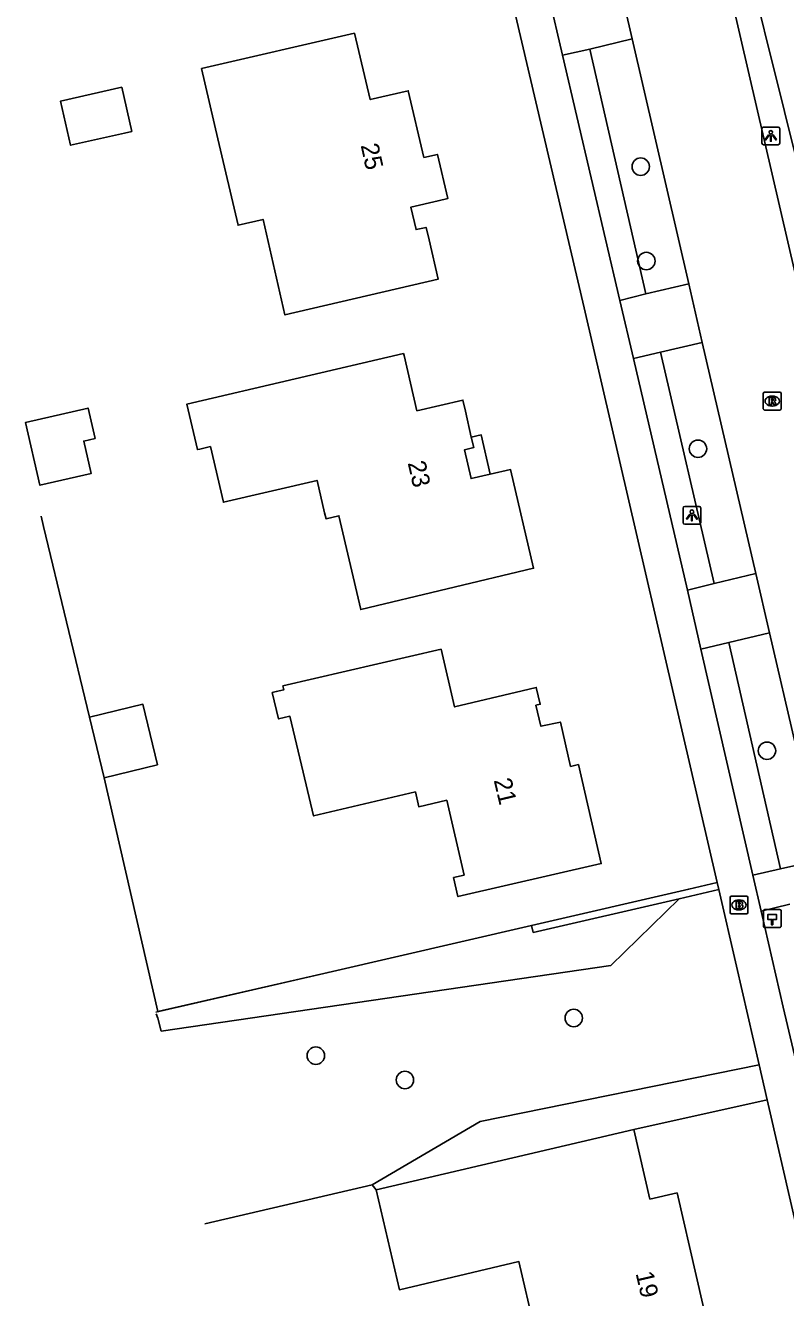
# Model space of a CAD drawing. Extents: x 156414 to 157775, y 382335 to 383765.
# Drawn here: x 156686.2 to 156728.9, y 382611 to 382682.4 of the extents above; entities that cross this region are included whole.
import ezdxf

# ---------------------------------------------------------------- set-up
doc = ezdxf.new("R2010")
doc.units = 0
for name, color, linetype in [('IMGEO_Boom', 7, 'Continuous'), ('IMGEO_Brandkraan', 7, 'Continuous'), ('IMGEO_Greppel_droge_sloot', 7, 'Continuous'), ('IMGEO_Groenvoorziening', 7, 'Continuous'), ('IMGEO_Haag', 7, 'Continuous'), ('IMGEO_Hectometerpaal', 7, 'Continuous'), ('IMGEO_Hek', 7, 'Continuous'), ('IMGEO_Lichtpunt', 7, 'Continuous'), ('IMGEO_Pand', 7, 'Continuous'), ('IMGEO_Pand_nummerreeks', 7, 'Continuous'), ('IMGEO_Pand_overbouw', 7, 'Continuous'), ('IMGEO_Parkeervlak_halfverhard', 7, 'Continuous'), ('IMGEO_Rijbaan_lokaal_gesloten', 7, 'Continuous'), ('IMGEO_Rijbaan_lokaal_open', 7, 'Continuous'), ('IMGEO_Rioolput', 7, 'Continuous'), ('IMGEO_Voetpad_open', 7, 'Continuous')]:
    doc.layers.add(name, color=color, linetype=linetype)

msp = doc.modelspace()

# ---------------------------------------------------------------- linework, layer by layer
at = {"layer": 'IMGEO_Boom'}
for centre in [(156720.732, 382674.429), (156721.049, 382669.132), (156723.946, 382658.599), (156727.819, 382641.649), (156716.972, 382626.649), (156702.493, 382624.535), (156707.495, 382623.172)]:
    msp.add_circle(centre, 0.489, dxfattribs=at)
at = {"layer": 'IMGEO_Brandkraan'}
for p, q in [((156725.749, 382632.57), (156725.749, 382633.422)), ((156725.824, 382633.496), (156726.676, 382633.496)), ((156726.237, 382633.276), (156726.262, 382633.276)), ((156726.75, 382633.422), (156726.75, 382632.57)), ((156726.676, 382632.496), (156725.824, 382632.496)), ((156726.26, 382632.716), (156726.235, 382632.716))]:
    msp.add_line(p, q, dxfattribs=at)
for points in [[(156725.749, 382632.57), (156725.749, 382633.422)], [(156725.824, 382633.496), (156726.676, 382633.496)], [(156726.097, 382633.196), (156726.097, 382632.796), (156726.31, 382632.796)], [(156726.328, 382633.196), (156726.097, 382633.196)], [(156726.276, 382633.115), (156726.222, 382633.115), (156726.222, 382633.039)], [(156726.222, 382633.039), (156726.275, 382633.039)], [(156726.75, 382633.422), (156726.75, 382632.57)], [(156726.676, 382632.496), (156725.824, 382632.496)], [(156726.284, 382632.963), (156726.222, 382632.963), (156726.222, 382632.882)], [(156726.222, 382632.882), (156726.284, 382632.882)]]:
    msp.add_lwpolyline(points, dxfattribs=at)
for centre, radius, start, end in [((156725.826, 382633.42), 0.0765, 91.55205, 178.44795), ((156725.826, 382633.42), 0.0765, 91.55205, 178.44795), ((156726.277, 382633.077), 0.0379, 267.82845, 90.93552), ((156726.332, 382633.051), 0.145, 59.4692, 91.53667), ((156726.357, 382633.098), 0.0922, 285.51372, 58.15012), ((156726.362, 382632.906), 0.105, 301.31148, 78.98903), ((156726.674, 382633.42), 0.0765, 1.55205, 88.44795), ((156726.674, 382633.42), 0.0765, 1.55205, 88.44795), ((156725.826, 382632.572), 0.0765, 181.55205, 268.44795), ((156725.826, 382632.572), 0.0765, 181.55205, 268.44795), ((156726.285, 382632.922), 0.0404, 269.87594, 90.50774), ((156726.316, 382633.047), 0.251, 268.66757, 293.53466), ((156726.674, 382632.572), 0.0765, 271.55205, 358.44795), ((156726.674, 382632.572), 0.0765, 271.55205, 358.44795)]:
    msp.add_arc(centre, radius, start, end, dxfattribs=at)
for centre, major_axis, ratio, start_param, end_param in [((156726.236, 382632.996), (-0.387, 0.002), 0.722429, 4.712389, 7.853982), ((156726.261, 382632.996), (-0.39, 0.002), 0.717154, 1.570796, 4.712389)]:
    msp.add_ellipse(centre, major_axis=major_axis, ratio=ratio, start_param=start_param, end_param=end_param, dxfattribs=at)
at = {"layer": 'IMGEO_Greppel_droge_sloot'}
msp.add_lwpolyline([(156737.852, 382641.163), (156726.53, 382686.636)], dxfattribs=at)
at = {"layer": 'IMGEO_Groenvoorziening'}
for points in [[(156693.53, 382626.892), (156693.617, 382626.638), (156693.819, 382625.918), (156719.051, 382629.606), (156722.881, 382633.345)], [(156693.51, 382626.977), (156703.184, 382629.211), (156714.604, 382631.846)], [(156705.651, 382617.283), (156711.711, 382620.85), (156727.385, 382624.03)], [(156727.839, 382622.057), (156720.348, 382620.401)], [(156705.651, 382617.283), (156696.258, 382615.091)], [(156705.872, 382617.015), (156705.651, 382617.283)]]:
    msp.add_lwpolyline(points, dxfattribs=at)
at = {"layer": 'IMGEO_Haag'}
for points in [[(156714.604, 382631.846), (156723.432, 382633.883), (156725.025, 382634.25)], [(156725.115, 382633.86), (156722.881, 382633.345)], [(156722.881, 382633.345), (156714.694, 382631.456), (156714.604, 382631.846)]]:
    msp.add_lwpolyline(points, dxfattribs=at)
at = {"layer": 'IMGEO_Hectometerpaal'}
for p, q in [((156727.617, 382632.648), (156727.617, 382631.807)), ((156727.617, 382632.648), (156727.617, 382631.807)), ((156728.533, 382632.732), (156727.692, 382632.732)), ((156728.533, 382632.732), (156727.692, 382632.732)), ((156728.617, 382631.816), (156728.617, 382632.657)), ((156728.617, 382631.816), (156728.617, 382632.657)), ((156727.701, 382631.732), (156728.542, 382631.732)), ((156727.701, 382631.732), (156728.542, 382631.732))]:
    msp.add_line(p, q, dxfattribs=at)
msp.add_lwpolyline([(156728.142, 382631.876), (156728.082, 382631.876), (156728.082, 382632.181), (156727.862, 382632.181), (156727.862, 382632.45), (156728.362, 382632.45), (156728.362, 382632.181), (156728.142, 382632.181), (156728.142, 382631.876)], dxfattribs=at)
for centre, start, end in [((156727.695, 382632.654), 92.4484, 184.28452), ((156727.695, 382632.654), 92.4484, 184.28452), ((156728.539, 382632.654), 2.4484, 94.28452), ((156728.539, 382632.654), 2.4484, 94.28452), ((156727.695, 382631.81), 182.4484, 274.28452), ((156727.695, 382631.81), 182.4484, 274.28452), ((156728.539, 382631.81), 272.4484, 4.28452), ((156728.539, 382631.81), 272.4484, 4.28452)]:
    msp.add_arc(centre, 0.0779, start, end, dxfattribs=at)
at = {"layer": 'IMGEO_Hek'}
for points in [[(156687.072, 382654.823), (156687.21, 382654.227)], [(156687.21, 382654.227), (156689.788, 382643.539)], [(156693.632, 382627.007), (156690.609, 382640.137)], [(156703.184, 382629.211), (156714.604, 382631.846)], [(156693.632, 382627.007), (156703.184, 382629.211)]]:
    msp.add_lwpolyline(points, dxfattribs=at)
at = {"layer": 'IMGEO_Lichtpunt'}
for p, q in [((156727.537, 382676.558), (156727.537, 382675.751)), ((156727.537, 382676.558), (156727.537, 382675.751)), ((156728.439, 382676.653), (156727.631, 382676.653)), ((156728.439, 382676.653), (156727.631, 382676.653)), ((156728.533, 382675.751), (156728.533, 382676.558)), ((156728.533, 382675.751), (156728.533, 382676.558)), ((156727.631, 382675.657), (156728.439, 382675.657)), ((156727.631, 382675.657), (156728.439, 382675.657)), ((156723.106, 382655.264), (156723.106, 382654.457)), ((156723.106, 382655.264), (156723.106, 382654.457)), ((156724.008, 382655.359), (156723.2, 382655.359)), ((156724.008, 382655.359), (156723.2, 382655.359)), ((156724.102, 382654.457), (156724.102, 382655.264)), ((156724.102, 382654.457), (156724.102, 382655.264)), ((156723.2, 382654.363), (156724.008, 382654.363)), ((156723.2, 382654.363), (156724.008, 382654.363))]:
    msp.add_line(p, q, dxfattribs=at)
for points in [[(156727.911, 382676.222), (156727.95, 382676.194), (156727.762, 382675.932), (156727.724, 382675.959), (156727.911, 382676.222)], [(156728.013, 382676.174), (156728.06, 382676.174), (156728.06, 382675.852), (156728.013, 382675.852), (156728.013, 382676.174)], [(156728.123, 382676.194), (156728.161, 382676.221), (156728.348, 382675.959), (156728.309, 382675.931), (156728.123, 382676.194)], [(156723.48, 382654.928), (156723.519, 382654.9), (156723.331, 382654.638), (156723.293, 382654.665), (156723.48, 382654.928)], [(156723.582, 382654.88), (156723.629, 382654.88), (156723.629, 382654.558), (156723.582, 382654.558), (156723.582, 382654.88)], [(156723.692, 382654.9), (156723.73, 382654.927), (156723.917, 382654.665), (156723.878, 382654.637), (156723.692, 382654.9)]]:
    msp.add_lwpolyline(points, dxfattribs=at)
for centre in [(156728.036, 382676.356), (156723.605, 382655.062)]:
    msp.add_circle(centre, 0.0994, dxfattribs=at)
for centre, start, end in [((156727.631, 382676.558), 90, 180), ((156727.631, 382676.558), 90, 180), ((156728.439, 382676.558), 0, 90), ((156728.439, 382676.558), 0, 90), ((156727.631, 382675.751), 180, 270), ((156727.631, 382675.751), 180, 270), ((156728.439, 382675.751), 270, 0), ((156728.439, 382675.751), 270, 360), ((156723.2, 382655.264), 90, 180), ((156723.2, 382655.264), 90, 180), ((156724.008, 382655.264), 0, 90), ((156724.008, 382655.264), 0, 90), ((156723.2, 382654.457), 180, 270), ((156723.2, 382654.457), 180, 270), ((156724.008, 382654.457), 270, 0), ((156724.008, 382654.457), 270, 360)]:
    msp.add_arc(centre, 0.0946, start, end, dxfattribs=at)
at = {"layer": 'IMGEO_Pand'}
for points in [[(156704.657, 382681.914), (156705.551, 382678.197), (156707.683, 382678.692), (156708.562, 382674.946), (156709.317, 382675.112), (156709.897, 382672.638), (156709.358, 382672.512), (156707.825, 382672.152), (156708.119, 382670.899), (156708.682, 382671.021), (156708.846, 382670.326), (156709.367, 382668.117), (156700.76, 382666.11), (156699.534, 382671.469), (156698.128, 382671.144), (156696.997, 382675.993), (156696.078, 382679.932), (156704.657, 382681.914)], [(156691.594, 382678.892), (156692.159, 382676.409), (156691.748, 382676.315), (156688.723, 382675.628), (156688.16, 382678.114), (156691.594, 382678.892)], [(156707.418, 382663.946), (156707.443, 382663.84), (156708.171, 382660.726), (156710.749, 382661.332), (156710.889, 382660.713), (156711.222, 382659.249), (156711.355, 382658.664), (156710.839, 382658.546), (156711.211, 382656.927), (156712.281, 382657.173), (156713.429, 382657.43), (156714.719, 382651.887), (156705.019, 382649.572), (156703.787, 382654.84), (156703.066, 382654.671), (156702.987, 382655.01), (156702.563, 382656.823), (156697.305, 382655.593), (156696.574, 382658.719), (156695.981, 382658.58), (156695.843, 382658.548), (156695.247, 382661.099), (156707.418, 382663.946)], [(156690.102, 382659.172), (156689.468, 382659.026), (156689.887, 382657.213), (156687.003, 382656.547), (156686.19, 382660.065), (156689.708, 382660.877), (156690.102, 382659.172)], [(156708.083, 382639.34), (156702.365, 382637.988), (156701.782, 382640.455), (156701.041, 382643.589), (156700.398, 382643.437), (156700.048, 382644.916), (156700.269, 382644.968), (156700.697, 382645.069), (156700.647, 382645.283), (156709.527, 382647.347), (156710.278, 382644.11), (156714.07, 382645.013), (156714.87, 382645.204), (156715.091, 382644.257), (156714.848, 382644.201), (156715.127, 382643.024), (156716.228, 382643.258), (156716.796, 382640.77), (156717.234, 382640.87), (156718.513, 382635.315), (156710.474, 382633.463), (156710.227, 382634.535), (156710.812, 382634.67), (156709.844, 382638.87), (156708.275, 382638.508), (156708.083, 382639.34)], [(156693.61, 382640.861), (156690.609, 382640.137), (156689.788, 382643.539), (156692.789, 382644.263), (156693.61, 382640.861)], [(156720.348, 382620.401), (156721.249, 382616.488), (156722.772, 382616.838), (156724.915, 382607.561), (156715.64, 382605.418), (156713.892, 382612.982), (156707.186, 382611.397), (156705.872, 382617.015)], [(156705.872, 382617.015), (156720.348, 382620.401)]]:
    msp.add_lwpolyline(points, dxfattribs=at)
at = {"layer": 'IMGEO_Pand_overbouw'}
msp.add_lwpolyline([(156712.281, 382657.173), (156711.779, 382659.373), (156711.222, 382659.249), (156711.355, 382658.664), (156710.839, 382658.546), (156711.211, 382656.927)], close=True, dxfattribs=at)
at = {"layer": 'IMGEO_Parkeervlak_halfverhard'}
for points in [[(156717.872, 382681.03), (156721.027, 382667.291)], [(156721.845, 382664.018), (156724.862, 382651.027)], [(156725.682, 382647.725), (156728.587, 382635.019)]]:
    msp.add_lwpolyline(points, dxfattribs=at)
at = {"layer": 'IMGEO_Rijbaan_lokaal_gesloten'}
for points in [[(156736.553, 382637.563), (156725.004, 382687.432)], [(156720.255, 382681.599), (156719.479, 382684.929)], [(156723.431, 382667.857), (156720.255, 382681.599)], [(156724.186, 382664.553), (156723.431, 382667.857)], [(156727.193, 382651.603), (156724.186, 382664.553)], [(156727.963, 382648.268), (156727.193, 382651.603)], [(156730.916, 382635.549), (156727.963, 382648.268)]]:
    msp.add_lwpolyline(points, dxfattribs=at)
at = {"layer": 'IMGEO_Rijbaan_lokaal_open'}
for points in [[(156715.565, 382684.002), (156716.343, 382680.694)], [(156720.255, 382681.599), (156717.872, 382681.03)], [(156716.343, 382680.694), (156717.872, 382681.03)], [(156721.027, 382667.291), (156719.564, 382666.914)], [(156721.027, 382667.291), (156723.431, 382667.857)], [(156719.564, 382666.914), (156720.326, 382663.671)], [(156724.186, 382664.553), (156721.845, 382664.018)], [(156720.326, 382663.671), (156721.845, 382664.018)], [(156724.862, 382651.027), (156727.193, 382651.603)], [(156724.862, 382651.027), (156723.353, 382650.655)], [(156723.353, 382650.655), (156724.101, 382647.349)], [(156727.963, 382648.268), (156725.682, 382647.725)], [(156724.101, 382647.349), (156725.682, 382647.725)]]:
    msp.add_lwpolyline(points, dxfattribs=at)
at = {"layer": 'IMGEO_Rioolput'}
for p, q in [((156727.614, 382660.846), (156727.614, 382661.698)), ((156727.689, 382661.772), (156728.541, 382661.772)), ((156728.102, 382661.552), (156728.127, 382661.552)), ((156728.615, 382661.698), (156728.615, 382660.846)), ((156728.125, 382660.992), (156728.1, 382660.992)), ((156728.541, 382660.772), (156727.689, 382660.772))]:
    msp.add_line(p, q, dxfattribs=at)
for points in [[(156727.614, 382660.846), (156727.614, 382661.698)], [(156727.689, 382661.772), (156728.541, 382661.772)], [(156728.615, 382661.698), (156728.615, 382660.846)], [(156728.203, 382661.47), (156727.951, 382661.472), (156727.951, 382661.072)], [(156727.951, 382661.072), (156728.075, 382661.072), (156728.075, 382661.234), (156728.086, 382661.234)], [(156728.129, 382661.391), (156728.075, 382661.391), (156728.075, 382661.31)], [(156728.075, 382661.31), (156728.127, 382661.31)], [(156728.133, 382661.205), (156728.204, 382661.072), (156728.344, 382661.072), (156728.279, 382661.198)], [(156728.541, 382660.772), (156727.689, 382660.772)]]:
    msp.add_lwpolyline(points, dxfattribs=at)
for centre, radius, start, end in [((156727.691, 382661.696), 0.0765, 91.55205, 178.44795), ((156727.691, 382661.696), 0.0765, 91.55205, 178.44795), ((156728.539, 382661.696), 0.0765, 1.55205, 88.44795), ((156728.539, 382661.696), 0.0765, 1.55205, 88.44795), ((156727.691, 382660.848), 0.0765, 181.55205, 268.44795), ((156727.691, 382660.848), 0.0765, 181.55205, 268.44795), ((156728.085, 382661.181), 0.0533, 26.02933, 88.69889), ((156728.111, 382661.499), 0.19, 274.7715, 282.96867), ((156728.135, 382661.295), 0.0964, 77.00612, 93.18647), ((156728.149, 382661.352), 0.0378, 276.66336, 79.67722), ((156728.202, 382661.36), 0.109, 350.36119, 89.41601), ((156728.2, 382661.36), 0.112, 277.58423, 350.98172), ((156728.184, 382661.145), 0.108, 29.51342, 73.79051), ((156728.539, 382660.848), 0.0765, 271.55205, 358.44795), ((156728.539, 382660.848), 0.0765, 271.55205, 358.44795)]:
    msp.add_arc(centre, radius, start, end, dxfattribs=at)
for centre, major_axis, ratio, start_param, end_param in [((156728.101, 382661.272), (-0.387, 0.002), 0.722429, 4.712389, 7.853982), ((156728.126, 382661.272), (-0.39, 0.002), 0.717154, 1.570796, 4.712389)]:
    msp.add_ellipse(centre, major_axis=major_axis, ratio=ratio, start_param=start_param, end_param=end_param, dxfattribs=at)
at = {"layer": 'IMGEO_Voetpad_open'}
for points in [[(156725.025, 382634.25), (156717.566, 382666.506), (156708.634, 382704.563), (156696.399, 382757.676)], [(156716.343, 382680.694), (156719.564, 382666.914)], [(156720.326, 382663.671), (156723.353, 382650.655)], [(156724.101, 382647.349), (156727.027, 382634.664)], [(156728.587, 382635.019), (156730.916, 382635.549)], [(156728.587, 382635.019), (156727.027, 382634.664)], [(156727.027, 382634.664), (156727.486, 382632.653)], [(156725.115, 382633.86), (156725.025, 382634.25)], [(156727.385, 382624.03), (156726.112, 382629.552), (156725.115, 382633.86)], [(156729.11, 382633.03), (156727.486, 382632.653)], [(156727.486, 382632.653), (156728.727, 382627.263), (156729.855, 382622.503)], [(156727.839, 382622.057), (156727.385, 382624.03)], [(156749.185, 382529.649), (156731.446, 382606.382), (156727.839, 382622.057)]]:
    msp.add_lwpolyline(points, dxfattribs=at)

# ---------------------------------------------------------------- texts
at = {"layer": 'IMGEO_Pand_nummerreeks'}
for s, rotation, p in [('25', 282.54584, (156705.004, 382675.629)), ('23', 282.94221, (156707.644, 382657.805)), ('21', 283.33825, (156712.474, 382639.997)), ('19', 283.06364, (156720.441, 382612.318))]:
    msp.add_text(s, height=1, rotation=rotation, dxfattribs=at).set_placement(p)

doc.saveas('drawing.dxf')
